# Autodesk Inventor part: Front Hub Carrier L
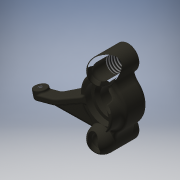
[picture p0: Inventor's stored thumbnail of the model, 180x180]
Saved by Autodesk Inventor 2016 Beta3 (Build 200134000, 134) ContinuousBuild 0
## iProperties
Shininess: 4.0
Length Units: 11272
Angle Units: 11279
Time Units: 11290
Mass Units: 11286
Length Display Precision: 3
Angle Display Precision: 2
Compacted: True
Company: Autodesk
Created: 2000-12
Part Number: Front Hub Carrier L
Document SubType Name: Modeling
Designer: Autodesk, Inc.
Project: Inventor Samples
User Status: IN PROGRESS
Material: Stiffzel
Density: 1.28 g/cm^3
Mass: 9.69759 g
Surface Area: 49.8526 cm^2
Volume: 7.57624 cm^3
Appearance: Stiffzel
Density: 1.28
Volumn: 7.576389013112748
Area: 49.85339250399974
PropertySet Name: Model Information
Control State: 0
Master: False
Checked Out: False
Last Check In Date: 2002-03-02
Last Check In By: Kevin.s
Author: Autodesk, Inc.
Revision Number: A
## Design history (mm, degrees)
sketch "Sketch1"
  geometry: L1 (6.351, 13.207)-(6.351, 8.171); L2 (-6.349, 13.207)-(-6.349, 8.171); L3 (-6.349, -18.861)-(-6.349, -13.826); L4 (6.351, -18.861)-(6.351, -13.826); C1 r 22.384 at (0.001, -2.827); A1 r 6.35 centre (0.001, 13.207) between (6.351, 13.207) and (-6.349, 13.207); A2 r 6.35 centre (0.001, -18.861) between (-6.349, -18.861) and (6.351, -18.861); A3 r 12.7 centre (0.001, -2.827) between (-6.349, 8.171) and (-6.349, -13.826); A4 r 12.7 centre (0.001, -2.827) between (6.351, -13.826) and (6.351, 8.171)
  constraints: 8 end point, 8 point on circle, 6 tangent, 5 centre point, 4 vertical alignment, 2 equal radius, 2 parallel, 2 vertical, 1 coincident, 1 other
  dimensions: "d0" = 44.7675 diameter of C1; "d2" = 12.7 diameter of A1; "d66" = 12.7 radius of A4
extrude "Extrusion1" new body sketch "Sketch1" distance "d4" = 14.2875; taper "d5" = 0 deg
fillet "Fillet1" dims "d6" = 6.35
workplane "Work Plane1"
sketch "Sketch3"
  geometry: L1 (-16.813, 46.821)-(-4.113, 46.821); A1 r 6.35 centre (-10.463, 46.821) between (-4.139, 47.402) and (-16.786, 47.399); A2 r 4.128 centre (-10.463, 46.821) between (-6.335, 46.821) and (-14.59, 46.821); A3 r 6.35 centre (-10.463, 46.821) between (-4.113, 46.821) and (-16.813, 46.821); 3 further points
  constraints: 9 point on circle, 3 centre point, 2 coincident, 2 end point, 2 point on line, 1 horizontal, 1 midpoint, 3 other
  dimensions: "d12" = 8.255 diameter of A2
revolve "Revolution1" sketch "Sketch3" stored, may be unused: angle "d11" = 180 deg
sketch "Sketch4"
  geometry: L1 (-16.838, 41.279)-(-4.138, 41.279); A1 r 6.35 centre (-10.488, 41.279) between (-4.155, 41.746) and (-16.821, 41.747); A2 r 4.128 centre (-10.488, 41.279) between (-6.361, 41.279) and (-14.616, 41.279); A3 r 6.35 centre (-10.488, 41.279) between (-4.138, 41.279) and (-16.838, 41.279); A4 r 6.35 centre (-10.488, 41.279) between (-5.281, 37.644) and (-15.677, 37.618); 3 further points
  constraints: 11 point on circle, 4 centre point, 3 coincident, 2 concentric, 2 end point, 2 point on line, 1 horizontal, 1 midpoint, 2 other
  dimensions: "d14" = 8.255 diameter of A2
revolve "Revolution2" sketch "Sketch4" stored, may be unused: angle "d13" = 180 deg
sketch "Sketch5"
  geometry: C1 r 9.525 at (0.001, -2.827); 3 further points
  constraints: 1 centre point, 1 coincident, 1 other
  dimensions: "d15" = 19.05 diameter of C1
extrude "Extrusion3" cut sketch "Sketch5" distance "d16" = 3.175; taper "d17" = 0 deg
sketch "Sketch6"
  geometry: C1 r 6.35 at (-0.001, -2.827); A1 r 12.7 centre (-0.001, -2.827) between (8.466, -12.293) and (8.466, 6.639) reference
  constraints: 1 centre point, 1 concentric
  dimensions: "d80" = 12.7 diameter of C1
extrude "Extrusion4" cut sketch "Sketch6" distance "d18" = 4.7625; taper "d19" = 0 deg
workplane "Work Plane2"
  workaxis "Work Axis1"
workplane "Work Plane3"
  workaxis "Work Axis2"
workplane "Work Plane4"
  workaxis "Work Axis3"
sketch "Sketch7"
  geometry: C1 r 4.127 at (0, 0) reference; C2 r 4.128 at (0, -32.068) reference
extrude "Extrusion5" cut sketch "Sketch7" stored distance "d24" = 3.175 (= d16); taper "d25" = 0 deg
sketch "Sketch8"
  geometry: L1 (4.082, -12.495)-(-4.173, -12.495); L2 (2.685, -15.591)-(2.685, -18.228); L3 (-2.776, -15.591)-(-2.776, -18.228); L4 (-12.303, -10.908)-(-12.303, -6.145) reference; L5 (-4.173, 1.792)-(4.082, 1.792) reference; A1 r 4.127 centre (-0.046, -12.495) between (-4.173, -12.495) and (4.082, -12.495); A2 r 6.35 centre (-0.046, -12.495) between (-6.396, -12.511) and (6.304, -12.511); A3 r 6.35 centre (-0.046, -12.495) between (-6.396, -12.495) and (6.304, -12.495) reference; A4 r 4.127 centre (-0.046, -12.495) between (-4.173, -12.495) and (4.082, -12.495) reference
  constraints: 9 point on circle, 6 end point, 3 concentric, 3 parallel, 2 centre point, 1 coincident, 1 midpoint, 1 perpendicular
  dimensions: "d27" = 5.461 distance between parallel lines of L2 L3
revolve "Revolution3" sketch "Sketch8" stored, may be unused: angle "d26" = 100 deg
sketch "Sketch9"
  geometry: L1 (5.053, -12.336)-(-3.202, -12.336); L2 (3.656, -15.432)-(3.656, -18.069); L3 (-1.805, -15.432)-(-1.805, -18.069); L4 (-3.202, 1.951)-(5.053, 1.951) reference; A1 r 4.128 centre (0.926, -12.336) between (-3.202, -12.336) and (5.053, -12.336); A2 r 6.35 centre (0.926, -12.336) between (-5.424, -12.336) and (7.276, -12.336); A3 r 4.128 centre (0.926, -12.336) between (-3.202, -12.336) and (5.053, -12.336) reference; A4 r 6.35 centre (0.926, -12.336) between (-5.424, -12.336) and (7.276, -12.336) reference
  constraints: 9 point on circle, 6 end point, 4 concentric, 3 parallel, 2 centre point, 1 midpoint, 1 perpendicular
  dimensions: "d29" = 5.461 distance between parallel lines of L2 L3
revolve "Revolution4" sketch "Sketch9" stored, may be unused: angle "d28" = 100 deg
fillet "Fillet3" dims "d30" = 2.54
sketch "Sketch16"
  geometry: L1 (-6.351, 13.207)-(-6.351, 11.372) reference; L2 (-6.351, -17.026)-(-6.351, -18.861) reference; L3 (6.349, -18.861)-(6.349, -17.026) reference; L4 (6.349, 11.372)-(6.349, 13.207) reference; C1 r 6.35 at (-0.001, -2.827) reference; C2 r 6.35 at (-0.001, 13.207); C3 r 6.35 at (-0.001, -18.861); A1 r 6.35 centre (-12.701, 11.372) between (-8.468, 6.639) and (-6.351, 11.372) reference; A2 r 12.7 centre (-0.001, -2.827) between (-8.468, 6.639) and (-8.468, -12.293) reference; A3 r 6.35 centre (-12.701, -17.026) between (-6.351, -17.026) and (-8.468, -12.293) reference; A4 r 6.35 centre (-0.001, -18.861) between (-6.351, -18.861) and (6.349, -18.861) reference; A5 r 6.35 centre (12.699, -17.026) between (8.466, -12.293) and (6.349, -17.026) reference; A6 r 12.7 centre (-0.001, -2.827) between (8.466, -12.293) and (8.466, 6.639) reference; A7 r 6.35 centre (12.699, 11.372) between (6.349, 11.372) and (8.466, 6.639) reference; A8 r 6.35 centre (-0.001, 13.207) between (6.349, 13.207) and (-6.351, 13.207) reference
  constraints: 2 centre point, 2 coincident, 2 tangent
extrude "Extrusion11" cut sketch "Sketch16" distance "d76" = 1.5875; taper "d77" = 0 deg
chamfer "Chamfer2" distance "d42" = 0.381; stored, may be unused: second distance "d43" = 0.381, angle "d148" = 45 deg
sketch "Sketch10"
  geometry: C1 r 6.032 at (0, 0); C2 r 6.35 at (0, 0) reference
  constraints: 1 centre point, 1 coincident
  dimensions: "d44" = 12.065 diameter of C1
extrude "Extrusion6" cut sketch "Sketch10" stored distance "d45" = 3.175 (= d16); taper "d46" = 0 deg
fillet "Fillet13" dims "d47" = 0.381
fillet "Fillet31" dims "d94" = 1.5875
fillet "Fillet32" dims "d95" = 0.381
fillet "Fillet33" dims "d96" = 0.3556
chamfer "Chamfer4" distance "d97" = 1.5875; stored, may be unused: second distance "d98" = 1.5875, angle "d149" = 45 deg
thread "Thread1" dims "d99" = 8.001, "d100" = 0
thread "Thread2" dims "d101" = 8.001, "d102" = 0
workplane "Work Plane5"
  workaxis "Work Axis4"
  workaxis "Work Axis5"
fillet "Fillet34" dims "d105" = 3.175
fillet "Fillet35" dims "d106" = 0.8128
fillet "Fillet36" dims "d107" = 0.8128
fillet "Fillet37" dims "d108" = 0.8128
sketch "Sketch19"
  geometry: L1 (-1.2, 14.287)-(9.525, 14.287) reference; L2 (11.957, 2.722)-(21.982, 14.669); L3 (21.982, 14.669)-(30.48, 14.668); L4 (30.48, 21.526)-(19.863, 21.526); L5 (19.863, 21.526)-(9.525, 14.287); L6 (9.525, 14.287)-(9.525, 1.587); L7 (0, -4.305)-(0, 25.832) reference; A1 r 3.175 centre (9.525, 4.763) between (9.525, 1.587) and (12.7, 4.763) reference; A2 r 3.429 centre (30.48, 18.098) between (30.48, 14.668) and (30.48, 21.526); 1 further point
  constraints: 10 end point, 3 point on circle, 3 tangent, 2 parallel, 1 centre point, 1 perpendicular
  dimensions: "d109" = 3.429 radius of A2; "d110" = 30.48 distance from line of A2.centre L7; "d111" = 55 deg angle of L5 L6; "d112" = 3.81 distance from line of L1 A2.centre; "d113" = 15 deg angle of L5 L2
extrude "Extrusion13" join sketch "Sketch19" stored distance "d114" = 3.175; taper "d115" = 0 deg
fillet "Fillet38" dims "d116" = 3.175
fillet "Fillet39" dims "d117" = 6.35
sketch "Sketch20"
  geometry: A1 r 3.429 centre (-30.48, -18.098) between (-30.48, -14.668) and (-30.48, -21.526) reference; 1 further point
  constraints: 1 coincident, 1 vertical alignment, 2 other
extrude "Extrusion14" join sketch "Sketch20" distance "d118" = 1.5875; taper "d119" = 0 deg
fillet "Fillet41" dims "d121" = 0.8128
fillet "Fillet42" dims "d122" = 0.8128
fillet "Fillet43" dims "d123" = 0.8128
sketch "Sketch21"
  geometry: C1 r 3.429 at (0, 0) reference
hole "Hole2" sketch "Sketch21" at (0, 0) diameter "d124" = 2.159; stored, may be unused: countersink angle "d128" = 60 deg, drill point angle "d130" = 118 deg; dims "d125" = 12.7, "d126" = 9.525, "d127" = 6.35, "d129" = 19.05
fillet "Fillet44" dims "d131" = 0.381
workplane "Work Plane6"
sketch "Sketch22"
  geometry: L1 (4.12, 15.883)-(-6.808, 2.04)
  constraints: 2 end point
feature "Rib1" sketch "Sketch22" dims "d132" = 2.54, "d133" = 2.54
fillet "Fillet45" dims "d134" = 1.27
fillet "Fillet46" dims "d135" = 1.27
sketch "Sketch23"
  geometry: A1 r 11.112 centre (0.001, -2.827) between (7.409, -11.11) and (7.409, 5.456) reference; A2 r 9.525 centre (0.001, -2.827) between (1.287, -12.265) and (1.287, 6.611) reference; A3 r 8.001 centre (3.113, -2.827) between (5.849, -10.346) and (5.849, 4.691)
  constraints: 4 point on circle, 1 centre point, 1 tangent, 1 vertical alignment
  dimensions: "d136" = 8.001 radius of A3
extrude "Extrusion15" join sketch "Sketch23" distance "d137" = 6.35; taper "d138" = 0 deg
fillet "Fillet47" dims "d140" = 3.175
fillet "Fillet48" dims "d141" = 0.8128
fillet "Fillet49" dims "d142" = 0.381
fillet "Fillet50" dims "d143" = 0.381
fillet "Fillet51" dims "d144" = 0.381
fillet "Fillet52" dims "d147" = 0.8128
body "Solid1"
feature "FaceDraft2" dims angle "d139" = 2.5 deg
other parameters: "d3" = 25.4, "d20" = 0, "d21" = 15 deg, "d22" = 0, "d23" = 0, "d48" = 0, "d49" = 0
